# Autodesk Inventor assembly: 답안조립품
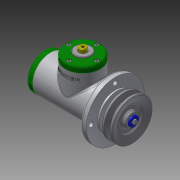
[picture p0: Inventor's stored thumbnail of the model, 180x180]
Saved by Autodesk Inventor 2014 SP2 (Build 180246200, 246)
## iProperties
Created: 2016-08
Part Number: 답안조립품
Document SubType Name: Assembly
Designer: 달림반
Author: 달림반
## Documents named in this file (25)
- C:\Users\달림반\Desktop\460807V1015\답안조립품.iam
- C:\Users\달림반\Desktop\460807V1015\1본체.ipt
- C:\Users\달림반\Desktop\460807V1015\V-벨트풀리.ipt
- C:\Users\달림반\Desktop\460807V1015\너트 M10.ipt
- C:\Users\달림반\Desktop\460807V1015\링크.ipt
- C:\Users\달림반\Desktop\460807V1015\멈춤링 15 x 1.ipt
- C:\Users\달림반\Desktop\460807V1015\멈춤링 35x1.6.ipt
- C:\Users\달림반\Desktop\460807V1015\베어링 15 x 35 x 11.ipt
- C:\Users\달림반\Desktop\460807V1015\볼트 M4 x 10.ipt
- C:\Users\달림반\Desktop\460807V1015\볼트 M4 x 12.ipt
- C:\Users\달림반\Desktop\460807V1015\부시1.ipt
- C:\Users\달림반\Desktop\460807V1015\부시2.ipt
- C:\Users\달림반\Desktop\460807V1015\분할핀 1.6 x 12.ipt
- C:\Users\달림반\Desktop\460807V1015\사이드 커버.ipt
- 사이드 커버.ipt
- C:\Users\달림반\Desktop\460807V1015\슬라이더.ipt
- C:\Users\달림반\Desktop\460807V1015\오일 실 15 25 7.ipt
- C:\Users\달림반\Desktop\460807V1015\와셔 4x16.ipt
- C:\Users\달림반\Desktop\460807V1015\와셔 10x21.ipt
- C:\Users\달림반\Desktop\460807V1015\클래스터 핀 6 x 24.ipt
- C:\Users\달림반\Desktop\460807V1015\키 4 x 4 x 18.ipt
- C:\Users\달림반\Desktop\460807V1015\탑 부시.ipt
- C:\Users\달림반\Desktop\460807V1015\탑 커버.ipt
- 탑 커버.ipt
- C:\Users\달림반\Desktop\460807V1015\편심축.ipt
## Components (7 placed, 4 different names)
1. 1본체:1
2. V-벨트풀리:1
3. ISO 4017 M4 x 10:1
4. ISO 4762 M4 x 12:1
5. ISO 4762 M4 x 12:2
6. ISO 4762 M4 x 12:3
7. ISO 4762 M4 x 12:4
